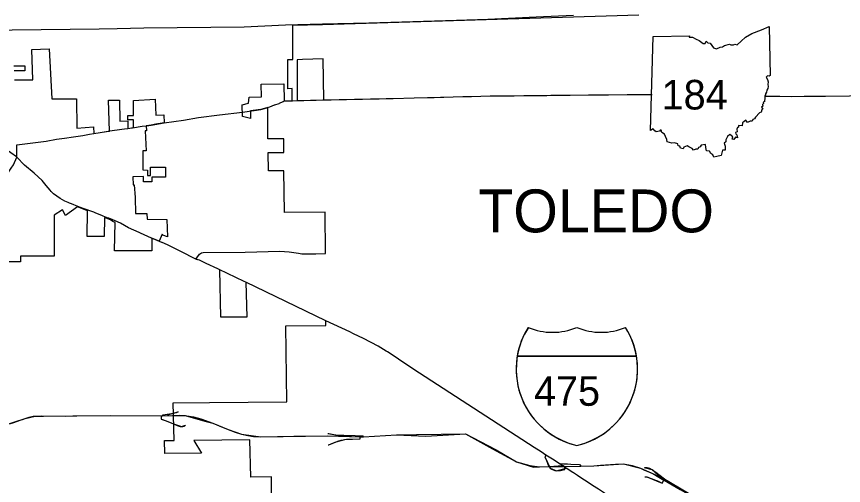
# Model space of a CAD drawing. Extents: x 0 to 750, y 0 to 507.
# Drawn here: x 255.1 to 327.4, y 296.1 to 337.1 of the extents above; entities that cross this region are included whole.
import ezdxf

# ---------------------------------------------------------------- set-up
doc = ezdxf.new("R2010")
doc.units = 0
for name, color, linetype in [('DV_X_Corp_Line', 7, 'Continuous'), ('GM_P_US_Alignment', 7, 'Continuous'), ('GM_X_Corporation_Text', 7, 'Continuous'), ('GM_X_County', 7, 'Continuous'), ('GM_X_Interchange_Ramps', 7, 'Continuous'), ('GM_X_Interstate_Route', 7, 'Continuous'), ('GM_X_State_Route', 7, 'Continuous')]:
    doc.layers.add(name, color=color, linetype=linetype)

msp = doc.modelspace()

# ---------------------------------------------------------------- linework, layer by layer
at = {"layer": 'DV_X_Corp_Line'}
for points in [[(277.395, 293.183), (277.361, 296.859), (275.532, 296.848), (275.457, 300.091), (270.552, 300.042), (271.218, 298.925), (268.022, 298.915), (267.986, 300.036), (268.835, 300.046), (268.757, 303.352), (271.943, 303.382), (278.687, 303.432), (278.592, 310.063), (282.1, 310.112), (282.092, 310.514), (275.097, 313.886), (275.188, 310.833), (272.926, 310.83), (272.839, 314.957), (272.651, 315.045), (271.641, 315.52), (271.064, 315.796), (271.048, 315.8), (270.906, 315.842), (270.811, 315.87), (270.804, 315.872), (270.731, 315.908), (271.054, 316.342), (271.135, 316.401), (271.231, 316.449), (271.367, 316.487), (275.061, 316.513), (278.093, 316.592), (278.886, 316.532), (279.722, 316.411), (280.001, 316.371), (280.3, 316.365), (281.224, 316.373), (282.088, 316.387), (282.043, 320.012), (278.481, 319.991), (278.436, 323.629), (277.085, 323.621), (277.075, 325.221), (278.426, 325.23), (278.419, 326.43), (277.043, 326.422), (277.027, 329.158), (276.412, 328.993), (275.507, 328.857), (275.512, 328.203), (274.811, 328.368), (274.783, 329.383), (275.349, 329.528), (275.395, 330.051), (276.477, 330.102), (276.46, 331.198), (278.424, 331.215), (278.452, 329.728), (279.162, 329.747), (279.162, 330.804), (278.794, 330.785), (278.794, 333.341), (279.231, 333.357), (279.23, 336.341), (281.799, 336.42), (296.121, 336.861), (309.484, 337.242)], [(254.881, 331.572), (256.475, 331.573), (256.386, 334.238), (257.907, 334.286), (258.151, 329.921), (258.97, 329.921), (259.832, 329.922), (260.288, 329.922), (260.331, 327.34), (261.792, 327.469), (261.819, 326.881), (262.926, 327.067), (263.173, 327.1), (263.107, 329.794), (264.045, 329.81), (264.076, 327.959), (264.773, 328.002), (264.791, 327.324), (265.283, 327.406), (265.283, 328.079), (264.781, 328.07), (264.781, 328.445), (265.283, 328.454), (265.282, 329.77), (267.186, 329.882), (267.222, 328.495), (267.943, 328.52), (267.956, 327.805), (267.243, 327.688), (266.829, 327.6), (266.393, 327.562), (266.42, 327.118), (266.296, 327.113), (266.404, 325.378), (266.108, 325.36), (266.108, 323.696), (266.519, 323.689), (266.519, 323.201), (266.769, 323.206), (266.769, 323.934), (268.076, 323.947), (268.089, 323.08), (266.892, 323.075), (266.892, 322.67), (266.144, 322.657), (266.144, 323.114), (265.231, 323.098), (265.248, 322.394), (265.352, 322.394), (265.435, 321.303), (265.446, 319.903), (266.442, 319.888), (266.478, 319.402), (268.2, 319.369), (268.245, 317.838), (267.852, 318.008), (267.793, 318.079), (267.54, 317.457), (266.896, 317.733), (266.896, 316.615), (263.635, 316.639), (263.667, 319.11), (263.483, 319.192), (263.271, 319.329), (262.752, 319.528), (262.731, 317.868), (261.23, 317.888), (261.25, 320.117), (260.378, 320.47), (259.34, 319.721), (259.081, 320.222), (258.345, 319.744), (258.346, 316.164), (255.407, 316.163), (255.407, 315.662), (248.414, 315.659)], [(254.822, 332.811), (255.778, 332.811), (255.786, 332.361), (254.844, 332.361)]]:
    msp.add_lwpolyline(points, dxfattribs=at)
msp.add_lwpolyline([(279.607, 329.758), (281.923, 329.82), (281.871, 333.417), (280.066, 333.354), (279.606, 333.337)], close=True, dxfattribs=at)
at = {"layer": 'GM_P_US_Alignment'}
for p, q in [((268.257, 302.287), (269.182, 302.555)), ((283.165, 300.489), (282.281, 300.633))]:
    msp.add_line(p, q, dxfattribs=at)
for points in [[(249.219, 236.614), (248.814, 240.716), (248.102, 247.343), (247.632, 251.233), (247.516, 253.545), (247.395, 263.332), (247.521, 274.256), (248.511, 282.211), (248.511, 282.211), (248.382, 282.254), (248.418, 286.54), (248.262, 289.495), (248.064, 293.827), (247.886, 297.091), (248.325, 298.001), (248.704, 298.832), (249.492, 299.601), (250.125, 299.961), (251.804, 300.69), (255.795, 301.978), (256.69, 302.166), (257.425, 302.18), (263.283, 302.22)], [(263.283, 302.22), (267.692, 302.208), (269.792, 302.229), (271.525, 301.748), (272.218, 301.559), (273.563, 301.009), (274.724, 300.603), (276.433, 300.364), (279.311, 300.437), (282.282, 300.455), (285.384, 300.358), (288.29, 300.55), (290.851, 300.412), (294.33, 300.634), (296.999, 299.227), (298.781, 298.174), (300.274, 297.714), (300.805, 297.751), (303.003, 297.783), (305.537, 297.842), (308.134, 298.004), (309.627, 297.615), (311.609, 296.75), (315.266, 294.587)], [(267.692, 302.208), (267.69, 301.902), (268.136, 301.778), (268.793, 301.506), (269.477, 301.27), (269.821, 301.379)], [(282.371, 299.676), (283.012, 299.944), (283.757, 300.138), (285.108, 300.196)], [(301.347, 298.772), (301.247, 298.617), (301.718, 297.635), (302.276, 297.409), (303.112, 297.636), (303.003, 297.783)], [(311.671, 296.587), (310.641, 297.481), (309.986, 297.657)], [(309.996, 296.875), (310.18, 296.877), (311.523, 296.328), (311.671, 296.587)]]:
    msp.add_lwpolyline(points, dxfattribs=at)
at = {"layer": 'GM_X_County'}
msp.add_lwpolyline([(174.879, 333.37), (188.864, 333.599), (201.627, 333.931), (211.161, 334.182), (214.509, 334.284), (230.891, 334.782), (238.555, 335.016), (243.643, 335.171), (252.35, 335.754), (254.675, 335.934), (262.292, 336.044), (263.849, 336.065), (266.19, 336.123), (274.975, 336.21), (278.568, 336.396), (281.798, 336.467), (285.861, 336.545), (293.537, 336.782), (296.285, 336.866), (300.489, 337.079), (303.777, 337.225)], dxfattribs=at)
at = {"layer": 'GM_X_Interchange_Ramps'}
for points in [[(269.182, 302.555), (269.013, 302.464), (268.767, 302.421), (267.867, 302.261), (267.828, 302.257), (267.827, 302.207)], [(267.692, 302.208), (267.69, 301.902), (267.828, 301.871), (268.136, 301.778), (268.636, 301.576), (268.793, 301.506), (269.102, 301.368), (269.264, 301.298), (269.364, 301.277), (269.477, 301.27), (269.584, 301.277), (269.699, 301.312), (269.821, 301.379)], [(285.384, 300.358), (285.383, 300.43), (284.674, 300.447), (283.687, 300.474), (283.165, 300.489), (282.95, 300.527), (282.354, 300.634), (282.281, 300.633)], [(282.295, 299.675), (282.371, 299.676), (282.636, 299.79), (283.012, 299.944), (283.253, 300.023), (283.456, 300.078), (283.623, 300.116), (283.757, 300.138), (283.914, 300.156), (284.304, 300.166), (285.108, 300.196), (285.107, 300.356)], [(301.347, 298.772), (301.247, 298.617), (301.282, 298.56), (301.367, 298.378), (301.513, 297.966), (301.61, 297.784), (301.625, 297.763), (301.718, 297.635), (301.858, 297.54), (301.99, 297.477), (302.121, 297.431), (302.276, 297.409), (302.435, 297.416), (302.617, 297.436), (302.979, 297.499), (303.007, 297.504), (303.004, 297.707), (303.003, 297.783)], [(304.4, 297.805), (304.398, 297.902), (304.294, 297.906), (303.524, 297.961), (303.247, 297.977), (302.93, 297.992), (302.629, 298.005), (302.603, 297.965)], [(311.692, 296.575), (311.736, 296.652), (311.609, 296.75), (310.958, 297.252), (310.922, 297.278), (310.641, 297.481), (310.444, 297.587), (310.22, 297.659), (309.986, 297.657)], [(309.996, 296.875), (310.18, 296.877), (310.558, 296.736), (310.924, 296.58), (311.098, 296.507), (311.523, 296.328), (311.671, 296.587)]]:
    msp.add_lwpolyline(points, dxfattribs=at)
at = {"layer": 'GM_X_Interstate_Route'}
for p, q in [((310.511, 327.152), (310.741, 335.359)), ((310.511, 327.152), (310.741, 335.359)), ((298.846, 307.433), (309.271, 307.433)), ((309.271, 307.433), (298.846, 307.433)), ((309.271, 307.433), (298.846, 307.433))]:
    msp.add_line(p, q, dxfattribs=at)
for points in [[(310.741, 335.359), (313.925, 335.413), (313.875, 335.314), (314.176, 335.293), (314.495, 335.118), (314.765, 335.007), (315.095, 334.746), (315.293, 334.749), (315.376, 334.963), (315.527, 334.798), (315.707, 334.768), (316.017, 334.375), (316.274, 334.29), (316.581, 334.425), (316.81, 334.447), (316.978, 334.58), (317.415, 334.694), (317.537, 334.626), (317.768, 334.639), (317.884, 334.69), (318.086, 334.645), (318.441, 334.943), (318.807, 335.295), (319.369, 335.627), (320.209, 335.942), (320.874, 336.223), (320.97, 331.964)], [(310.741, 335.359), (313.925, 335.413), (313.875, 335.314), (314.176, 335.293), (314.495, 335.118), (314.765, 335.007), (315.095, 334.746), (315.293, 334.749), (315.376, 334.963), (315.527, 334.798), (315.707, 334.768), (316.017, 334.375), (316.274, 334.29), (316.581, 334.425), (316.81, 334.447), (316.978, 334.58), (317.415, 334.694), (317.537, 334.626), (317.768, 334.639), (317.884, 334.69), (318.086, 334.645), (318.441, 334.943), (318.807, 335.295), (319.369, 335.627), (320.209, 335.942), (320.874, 336.223), (320.97, 331.964)], [(320.97, 331.964), (320.872, 331.904), (320.719, 331.932), (320.616, 331.813), (320.743, 331.613), (320.803, 331.403), (320.75, 331.171), (320.803, 330.979), (320.767, 330.819), (320.671, 330.66), (320.638, 330.508), (320.556, 330.348), (320.563, 330.258), (320.485, 330.187), (320.499, 329.92), (320.46, 329.773), (320.474, 329.646), (320.348, 329.612), (320.376, 329.507), (320.296, 329.426), (320.313, 329.286), (320.222, 329.197), (320.311, 329.018), (320.24, 328.961), (320.181, 328.744), (320.019, 328.7), (319.695, 328.302), (319.581, 328.152), (319.453, 328.115), (319.382, 327.96), (319.224, 327.96), (318.985, 327.853), (318.83, 328.037), (318.559, 327.815), (318.528, 327.56), (318.185, 327.568), (318.199, 327.438), (318.122, 327.401), (318.053, 327.271), (318.093, 327.041), (317.933, 326.982), (317.952, 326.848), (318.055, 326.766), (318.101, 326.511), (317.93, 326.563), (317.79, 326.347), (317.647, 326.398), (317.694, 326.58), (317.451, 326.8), (317.222, 326.624), (317.102, 326.343), (317.101, 326.154), (316.93, 326.04), (317.039, 325.773), (317.019, 325.589), (317.023, 325.415), (316.809, 325.421), (316.679, 324.95)], [(320.97, 331.964), (320.872, 331.904), (320.719, 331.932), (320.616, 331.813), (320.743, 331.613), (320.803, 331.403), (320.75, 331.171), (320.803, 330.979), (320.767, 330.819), (320.671, 330.66), (320.638, 330.508), (320.556, 330.348), (320.563, 330.258), (320.485, 330.187), (320.499, 329.92), (320.46, 329.773), (320.474, 329.646), (320.348, 329.612), (320.376, 329.507), (320.296, 329.426), (320.313, 329.286), (320.222, 329.197), (320.311, 329.018), (320.24, 328.961), (320.181, 328.744), (320.019, 328.7), (319.695, 328.302), (319.581, 328.152), (319.453, 328.115), (319.382, 327.96), (319.224, 327.96), (318.985, 327.853), (318.83, 328.037), (318.559, 327.815), (318.528, 327.56), (318.185, 327.568), (318.199, 327.438), (318.122, 327.401), (318.053, 327.271), (318.093, 327.041), (317.933, 326.982), (317.952, 326.848), (318.055, 326.766), (318.101, 326.511), (317.93, 326.563), (317.79, 326.347), (317.647, 326.398), (317.694, 326.58), (317.451, 326.8), (317.222, 326.624), (317.102, 326.343), (317.101, 326.154), (316.93, 326.04), (317.039, 325.773), (317.019, 325.589), (317.023, 325.415), (316.809, 325.421), (316.679, 324.95)], [(316.679, 324.95), (316.308, 324.86), (316.05, 324.806), (315.959, 325.02), (315.774, 325.133), (315.654, 325.348), (315.39, 325.377), (315.327, 325.673), (315.297, 325.914), (314.935, 325.854), (314.836, 325.707), (314.707, 325.668), (314.633, 325.52), (314.457, 325.508), (314.27, 325.438), (314.147, 325.583), (313.839, 325.729), (313.7, 325.804), (313.411, 325.687), (313.349, 325.549), (313.119, 325.61), (313.065, 325.764), (312.925, 325.81), (312.895, 325.974), (312.597, 326.061), (312.369, 326.026), (311.967, 326.158), (311.942, 326.373), (311.805, 326.635), (311.734, 326.817), (311.48, 326.956), (311.428, 327.172), (311.347, 327.166), (311.273, 327.078), (310.991, 327.038), (310.878, 327.126), (310.72, 327.277), (310.511, 327.152)], [(316.679, 324.95), (316.308, 324.86), (316.05, 324.806), (315.959, 325.02), (315.774, 325.133), (315.654, 325.348), (315.39, 325.377), (315.327, 325.673), (315.297, 325.914), (314.935, 325.854), (314.836, 325.707), (314.707, 325.668), (314.633, 325.52), (314.457, 325.508), (314.27, 325.438), (314.147, 325.583), (313.839, 325.729), (313.7, 325.804), (313.411, 325.687), (313.349, 325.549), (313.119, 325.61), (313.065, 325.764), (312.925, 325.81), (312.895, 325.974), (312.597, 326.061), (312.369, 326.026), (311.967, 326.158), (311.942, 326.373), (311.805, 326.635), (311.734, 326.817), (311.48, 326.956), (311.428, 327.172), (311.347, 327.166), (311.273, 327.078), (310.991, 327.038), (310.878, 327.126), (310.72, 327.277), (310.511, 327.152)], [(254.508, 301.539), (254.53, 301.545), (254.733, 301.597), (255.452, 301.843), (255.574, 301.891)], [(255.574, 301.891), (255.795, 301.978), (256.171, 302.074), (256.507, 302.165), (257.227, 302.207), (259.331, 302.184), (259.97, 302.19), (259.978, 302.19)], [(259.978, 302.19), (263.283, 302.22), (267.692, 302.208), (267.827, 302.207), (268.706, 302.24)], [(268.706, 302.24), (268.772, 302.242), (269.334, 302.264)], [(269.334, 302.264), (269.792, 302.229), (270.124, 302.184)], [(270.124, 302.184), (270.165, 302.179), (270.517, 302.105), (271.158, 301.941), (272.218, 301.559), (273.121, 301.196), (273.563, 301.009), (274.16, 300.782), (274.724, 300.603), (275.272, 300.486), (275.784, 300.404), (276.433, 300.364), (282.282, 300.455)], [(282.282, 300.455), (282.282, 300.455), (285.107, 300.356), (285.384, 300.358), (288.29, 300.55), (290.036, 300.574)], [(290.051, 300.574), (294.33, 300.634), (296.69, 299.318), (298.781, 298.174)], [(298.781, 298.174), (299.945, 297.867), (300.805, 297.751), (301.625, 297.763), (302.82, 297.865)], [(305.537, 297.842), (306.13, 297.878), (307.433, 297.968), (307.641, 297.978), (308.134, 298.004), (308.909, 297.87), (309.627, 297.615), (309.988, 297.462), (310.509, 297.248), (310.923, 297.013), (311.671, 296.587)], [(302.82, 297.865), (303.003, 297.783), (304.4, 297.805), (305.537, 297.842)], [(311.671, 296.587), (311.692, 296.575), (313.098, 295.775), (313.777, 295.389), (315.952, 294.081), (316.188, 293.94)]]:
    msp.add_lwpolyline(points, dxfattribs=at)
for centre, radius, start, end in [((305.6, 306.285), 6.851, 147.82161, 256.99413), ((305.172, 306.404), 6.409, 146.65397, 170.75899), ((301.93, 314.969), 5.467, 247.08482, 292.91053), ((301.93, 314.969), 5.467, 247.08482, 292.91053), ((302.517, 306.285), 6.851, 283.00654, 32.17868), ((306.187, 314.97), 5.468, 247.09162, 292.90836), ((306.187, 314.97), 5.468, 247.09162, 292.90836), ((302.517, 306.285), 6.851, 9.64753, 32.17902), ((305.6, 306.285), 6.851, 170.35136, 256.9967), ((302.531, 306.282), 6.838, 282.76665, 9.68983)]:
    msp.add_arc(centre, radius, start, end, dxfattribs=at)
at = {"layer": 'GM_X_State_Route'}
for points in [[(279.756, 329.762), (280.173, 329.773), (281.262, 329.802), (281.849, 329.829)], [(281.849, 329.829), (282.569, 329.833), (283.266, 329.847), (283.914, 329.86), (284.611, 329.874), (285.315, 329.888), (286.004, 329.901), (286.761, 329.917), (287.383, 329.929), (287.988, 329.945), (289.82, 329.992), (290.99, 330.022), (291.579, 330.037), (292.141, 330.052), (292.164, 330.052), (292.413, 330.059), (293.247, 330.081), (294.082, 330.103), (294.856, 330.124), (295.67, 330.146), (296.487, 330.168)], [(296.487, 330.168), (296.487, 330.168), (297.571, 330.179), (298.488, 330.188), (298.574, 330.189), (299.426, 330.198), (300.139, 330.206), (301, 330.215), (301.437, 330.219), (301.783, 330.223), (302.57, 330.231), (303.157, 330.237), (303.468, 330.24), (305.068, 330.257), (305.638, 330.263), (306.788, 330.275), (306.823, 330.275)], [(306.823, 330.275), (308.463, 330.292), (309.468, 330.303), (310.636, 330.287)], [(320.598, 330.15), (320.658, 330.15), (321.814, 330.134), (322.842, 330.12), (323.926, 330.135), (325.804, 330.16), (327.917, 330.189), (328.693, 330.2)], [(275.793, 328.896), (275.845, 328.904), (276.412, 328.993), (276.951, 329.135)], [(276.951, 329.135), (277.01, 329.151), (277.216, 329.205), (277.628, 329.396), (277.647, 329.402), (278.02, 329.517), (278.038, 329.526), (278.368, 329.687), (278.373, 329.689)], [(278.373, 329.689), (278.452, 329.728), (279.154, 329.746), (279.199, 329.748)], [(279.199, 329.748), (279.683, 329.76), (279.756, 329.762)], [(267.956, 327.805), (269.645, 328.059), (270.964, 328.268), (272.793, 328.527), (274.803, 328.742)], [(274.803, 328.742), (275.793, 328.896)], [(266.406, 327.563), (266.813, 327.598), (267.956, 327.805)], [(261.823, 326.881), (262.189, 326.941), (262.704, 327.029), (262.906, 327.063), (263.225, 327.106)], [(263.225, 327.106), (264.269, 327.248)], [(264.269, 327.248), (264.5, 327.279), (264.791, 327.324)], [(264.791, 327.324), (265.13, 327.38), (265.194, 327.391)], [(265.194, 327.391), (266.028, 327.53), (266.406, 327.563)], [(255.081, 325.89), (257.639, 326.213), (258.544, 326.38), (259.238, 326.483), (260.039, 326.582), (260.838, 326.721), (261.442, 326.819), (261.823, 326.881)], [(255.068, 324.815), (255.037, 324.837), (254.542, 325.189), (254.18, 325.466)], [(255.068, 324.815), (255.081, 325.89)], [(252.661, 321.839), (253.253, 322.442), (253.881, 323.071), (254.341, 323.517), (254.59, 323.846), (254.779, 324.154), (255.068, 324.815)], [(258.004, 321.916), (257.654, 322.343), (257.289, 322.763), (256.608, 323.402), (255.763, 324.128), (255.068, 324.815)], [(259.869, 320.724), (259.698, 320.792), (259.573, 320.844), (259.263, 320.973), (258.878, 321.19), (258.299, 321.621), (258.092, 321.809), (258.004, 321.916)], [(260.891, 320.325), (260.73, 320.383), (260.425, 320.504), (259.869, 320.724)], [(261.807, 319.992), (260.891, 320.325)], [(262.638, 319.658), (262.571, 319.684), (261.921, 319.95), (261.807, 319.992)], [(263.12, 319.471), (263.077, 319.489), (262.638, 319.658)], [(266.599, 317.861), (266.55, 317.882), (265.894, 318.169), (265.767, 318.225), (264.856, 318.626), (264.137, 319.048), (263.675, 319.237), (263.408, 319.352), (263.12, 319.471)], [(267.789, 317.349), (267.775, 317.355), (266.599, 317.861)], [(270.731, 315.908), (269.412, 316.559), (268.265, 317.145), (267.789, 317.349)], [(272.774, 314.987), (272.651, 315.045), (271.641, 315.52), (271.05, 315.8), (270.731, 315.908)], [(274.957, 313.953), (274.244, 314.297), (272.774, 314.987)], [(282.092, 310.514), (275.097, 313.886), (274.957, 313.953)], [(284.535, 309.384), (284.212, 309.541), (282.092, 310.514)], [(287.496, 307.794), (287.388, 307.866), (286.69, 308.305), (285.399, 308.961), (284.535, 309.384)], [(300.332, 299.423), (290.297, 305.93), (289.447, 306.497), (288.455, 307.156), (287.721, 307.645), (287.496, 307.794)], [(301.918, 298.405), (301.347, 298.772), (300.925, 299.043), (300.332, 299.423), (299.919, 299.689)], [(303.038, 297.684), (303.004, 297.707), (302.82, 297.865), (302.603, 297.965), (301.918, 298.405)], [(303.753, 297.218), (303.694, 297.257), (303.112, 297.636), (303.038, 297.684)], [(313.503, 290.864), (313.421, 290.918), (312.522, 291.503), (311.89, 291.916), (311.227, 292.348), (310.351, 292.918), (309.696, 293.345), (309.033, 293.777), (308.614, 294.051), (308.219, 294.308), (307.682, 294.658), (307.577, 294.726), (306.822, 295.218), (305.96, 295.78), (305.436, 296.122), (305.129, 296.321), (304.734, 296.579), (304.319, 296.849), (304.11, 296.985), (303.753, 297.218)]]:
    msp.add_lwpolyline(points, dxfattribs=at)

# ---------------------------------------------------------------- texts
at = {"layer": 'GM_X_Corporation_Text'}
msp.add_text('TOLEDO', height=3.7501, rotation=0.00001, dxfattribs=at).set_placement((295.435, 318.241))
at = {"layer": 'GM_X_Interstate_Route'}
for s, p in [('184', (311.475, 328.982)), ('475', (300.313, 303.082))]:
    msp.add_text(s, height=2.5875, dxfattribs=at).set_placement(p)

doc.saveas('drawing.dxf')
